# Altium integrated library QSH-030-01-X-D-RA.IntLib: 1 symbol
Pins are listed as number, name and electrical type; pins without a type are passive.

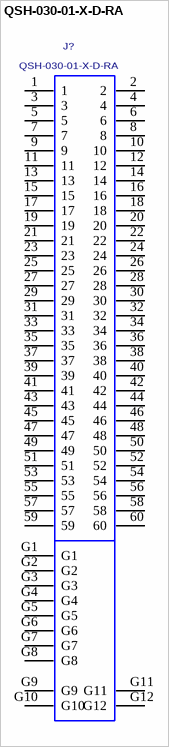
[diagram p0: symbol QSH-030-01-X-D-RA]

## QSH-030-01-X-D-RA
designator J?
.50mm DOUBLE ROW RIGHT ANGLE SOCKET STRIP.; MANUFACTURER: SAMTEC
footprint QSH-030-01-X-D-RA
pins: 1, 2, 3, 4, 5, 6, 7, 8, 9, 10, 11, 12, 13, 14, 15, 16, 17, 18, 19, 20, 21, 22, 23, 24, 25, 26, 27, 28, 29, 30, 31, 32, 33, 34, 35, 36, 37, 38, 39, 40, 41, 42, 43, 44, 45, 46, 47, 48, 49, 50, 51, 52, 53, 54, 55, 56, 57, 58, 59, 60, G1, G2, G3, G4, G5, G6, G7, G8, G9, G10, G11, G12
